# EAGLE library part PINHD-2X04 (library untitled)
PIN HEADER
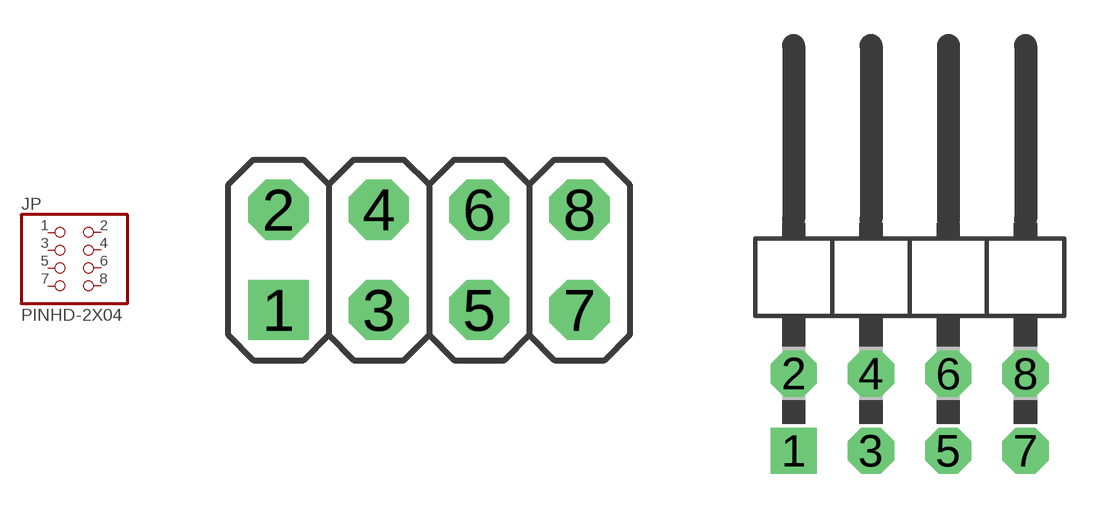
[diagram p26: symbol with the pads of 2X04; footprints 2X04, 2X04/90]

Designator prefix JP

## PINHD-2X04_2.54  [2X04]
1  1  pas
2  2  pas
3  3  pas
4  4  pas
5  5  pas
6  6  pas
7  7  pas
8  8  pas

## PINHD-2X04_2.54-90°  [2X04/90]
Pads as for 2X04

## PINHD-2X04_2.00  [2X04M]
Pads as for 2X04

## PINHD-2X04_2.54-SMD  [2X04SMD]
Pads as for 2X04

## PINHD-2X04_MICROMATCH  [MICROMATCH-8]
Pads as for 2X04

## PINHD-2X04_2.54-SMD-90°  [2X04SMD/90]
Pads as for 2X04

## Footprint 2X04 (pad centres in mm)
PIN HEADER - 2.54
drill 1.016 square: 1 -3.81,-1.27
drill 1.016 octagon: 2 -3.81,1.27; 3 -1.27,-1.27; 4 -1.27,1.27; 5 1.27,-1.27; 6 1.27,1.27; 7 3.81,-1.27; 8 3.81,1.27

## Footprint 2X04/90 (pad centres in mm)
PIN HEADER - 2.54 90°
drill 1.016 square: 1 -3.81,-6.35
drill 1.016 octagon: 2 -3.81,-3.81; 3 -1.27,-6.35; 4 -1.27,-3.81; 5 1.27,-6.35; 6 1.27,-3.81; 7 3.81,-6.35; 8 3.81,-3.81

## Footprint 2X04M (pad centres in mm)
PIN HEADER - 2
drill 0.914 square: 1 -3,-1
drill 0.914 round: 2 -3,1; 3 -1,-1; 4 -1,1; 5 1,-1; 6 1,1; 7 3,-1; 8 3,1

## Footprint 2X04SMD (pad centres in mm)
PIN HEADER - 2.54 SMD
smd 1.016 x 3.302: 1 -1.27,-3.81; 2 -1.27,1.27; 3 1.27,-3.81; 4 1.27,1.27; 5 3.81,-3.81; 6 3.81,1.27; 7 6.35,-3.81; 8 6.35,1.27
